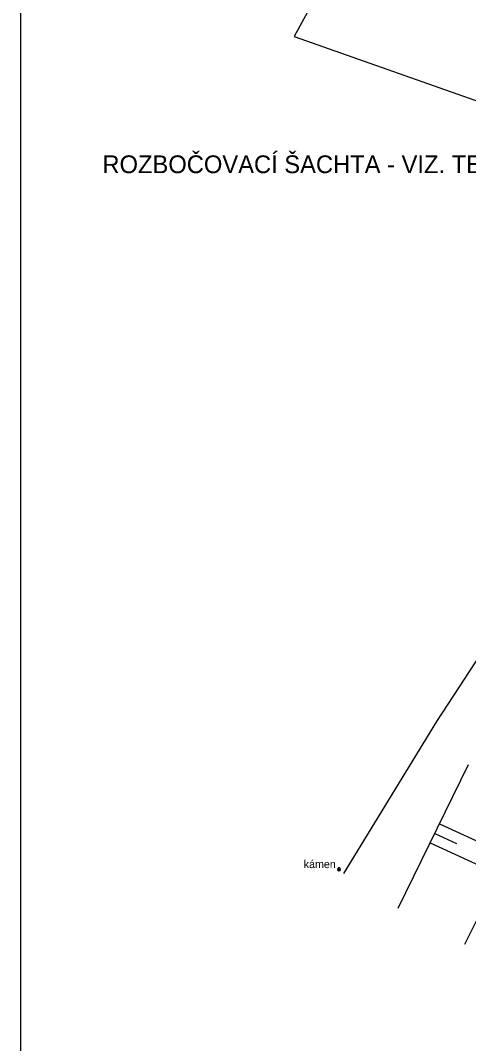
# Model space of a CAD drawing. Extents: x -517788 to -517166, y -1177087 to -1176790.
# Drawn here: x -517375.9 to -517350.6, y -1177027.2 to -1176969.6 of the extents above; entities that cross this region are included whole.
import ezdxf

# ---------------------------------------------------------------- set-up
doc = ezdxf.new("R2010")
doc.units = 0
for name, color, linetype in [('chodníky_obrubnik_schody', 7, 'Continuous'), ('hrany svahu', 7, 'Continuous'), ('mapove znacky', 7, 'Continuous'), ('označení lomového bodu', 7, 'Continuous'), ('porost', 7, 'Continuous'), ('Povrchy_popis', 7, 'Continuous'), ('šrafy', 7, 'Continuous')]:
    doc.layers.add(name, color=color, linetype=linetype)

msp = doc.modelspace()

# ---------------------------------------------------------------- linework, layer by layer
at = {"layer": 'chodníky_obrubnik_schody'}
msp.add_line((-517346.568, -1177012.94), (-517350.878, -1177021.61), dxfattribs=at)
at = {"layer": 'hrany svahu'}
msp.add_line((-517354.608, -1177019.56), (-517350.648, -1177011.47), dxfattribs=at)
msp.add_lwpolyline([(-517325.778, -1176972.12), (-517334.418, -1176968.19), (-517337.708, -1176966.57), (-517345.168, -1176963.26), (-517349.438, -1176961.09), (-517351.728, -1176960.5), (-517354.598, -1176961.07), (-517356.288, -1176962.82), (-517360.478, -1176970.47)], dxfattribs=at)
at = {"layer": 'mapove znacky'}
for radius in [0.0683, 0.0119]:
    msp.add_circle((-517357.948, -1177017.4), radius, dxfattribs=at)
msp.add_arc((-517357.948, -1177017.346), 0.0652, 339.29907, 201.87982, dxfattribs=at)
at = {"layer": 'označení lomového bodu'}
msp.add_lwpolyline([(-517375.912, -1176938.722), (-517375.912, -1177087.222), (-517165.912, -1177087.222), (-517165.912, -1176938.722)], dxfattribs=at)
at = {"layer": 'porost'}
for p, q in [((-517360.478, -1176970.47), (-517348.798, -1176974.6)), ((-517345.088, -1176997.73), (-517352.448, -1177009.04)), ((-517352.448, -1177009.04), (-517357.698, -1177017.61))]:
    msp.add_line(p, q, dxfattribs=at)
at = {"layer": 'šrafy'}
for p, q in [((-517352.282, -1177014.809), (-517348.385, -1177016.596)), ((-517352.546, -1177015.348), (-517351.325, -1177015.908)), ((-517352.81, -1177015.887), (-517348.92, -1177017.671))]:
    msp.add_line(p, q, dxfattribs=at)

# ---------------------------------------------------------------- texts
at = {"layer": 'označení lomového bodu'}
msp.add_text('ROZBOČOVACÍ ŠACHTA - VIZ. TECHNICKÁ ZPRÁVA', height=1, rotation=360, dxfattribs=at).set_placement((-517371.289, -1176978.17))
at = {"layer": 'Povrchy_popis'}
msp.add_text('kámen', height=0.45, dxfattribs=at).set_placement((-517359.941, -1177017.302))

doc.saveas('drawing.dxf')
